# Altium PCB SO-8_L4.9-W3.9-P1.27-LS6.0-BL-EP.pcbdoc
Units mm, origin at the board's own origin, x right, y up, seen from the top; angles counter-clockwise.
Board outline 17.77 x 20.3 mm, 2 copper layers (Top Layer, Bottom Layer), stack 0 mm thick; 1 components, 0 nets, 9 pads, 0 vias.
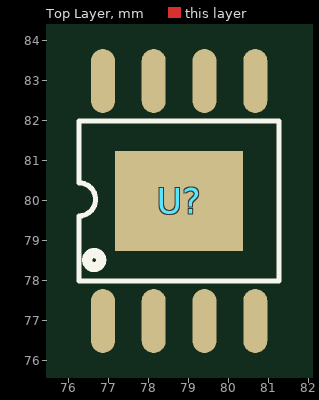
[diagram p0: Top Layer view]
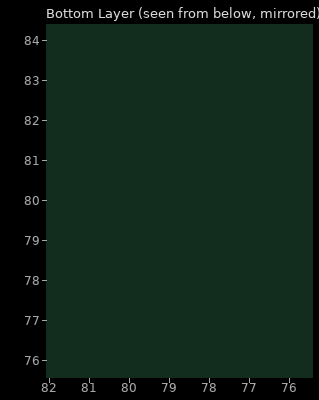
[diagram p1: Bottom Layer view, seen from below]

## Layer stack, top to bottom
Top Layer: signal copper (thickness not stored)
Bottom Layer: signal copper (thickness not stored)

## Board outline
87.616,69.85 69.85,69.85 69.85,90.15 87.616,90.15

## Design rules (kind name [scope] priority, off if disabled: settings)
PasteMaskExpansion "Paste Mask Expansion" [All] p1: expansion=0
SolderMaskExpansion "Solder Mask Expansion" [IsVia] p1: expansion=-25.4 istentingtop=TRUE
SolderMaskExpansion "Solder Mask Expansion" [All] p2: expansion=0.051 istentingtop=FALSE

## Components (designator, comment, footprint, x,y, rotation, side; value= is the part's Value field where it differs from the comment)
U? "" SO-8_L4.9-W3.9-P1.27-LS6.0-BL-EP 78.766,80 r0 top

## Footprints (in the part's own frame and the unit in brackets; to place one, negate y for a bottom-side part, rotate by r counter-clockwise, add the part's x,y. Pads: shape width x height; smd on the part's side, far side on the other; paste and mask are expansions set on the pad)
SO-8_L4.9-W3.9-P1.27-LS6.0-BL-EP [mm]
  oval 0.6x1.6 smd: 1(-1.905,-3) 2(-0.635,-3) 3(0.635,-3) 4(1.905,-3) 5(1.905,3) 6(0.635,3) 7(-0.635,3) 8(-1.905,3)
  rect 3.2x2.5 smd: 9(0,0)
  silkscreen extent -2.5,-2 2.5,2

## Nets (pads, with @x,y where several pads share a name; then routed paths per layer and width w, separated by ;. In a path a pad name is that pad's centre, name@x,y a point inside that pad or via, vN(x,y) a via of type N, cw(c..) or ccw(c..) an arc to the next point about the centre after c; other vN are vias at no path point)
pads on no net: U?.1 U?.2 U?.3 U?.4 U?.5 U?.6 U?.7 U?.8 U?.9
